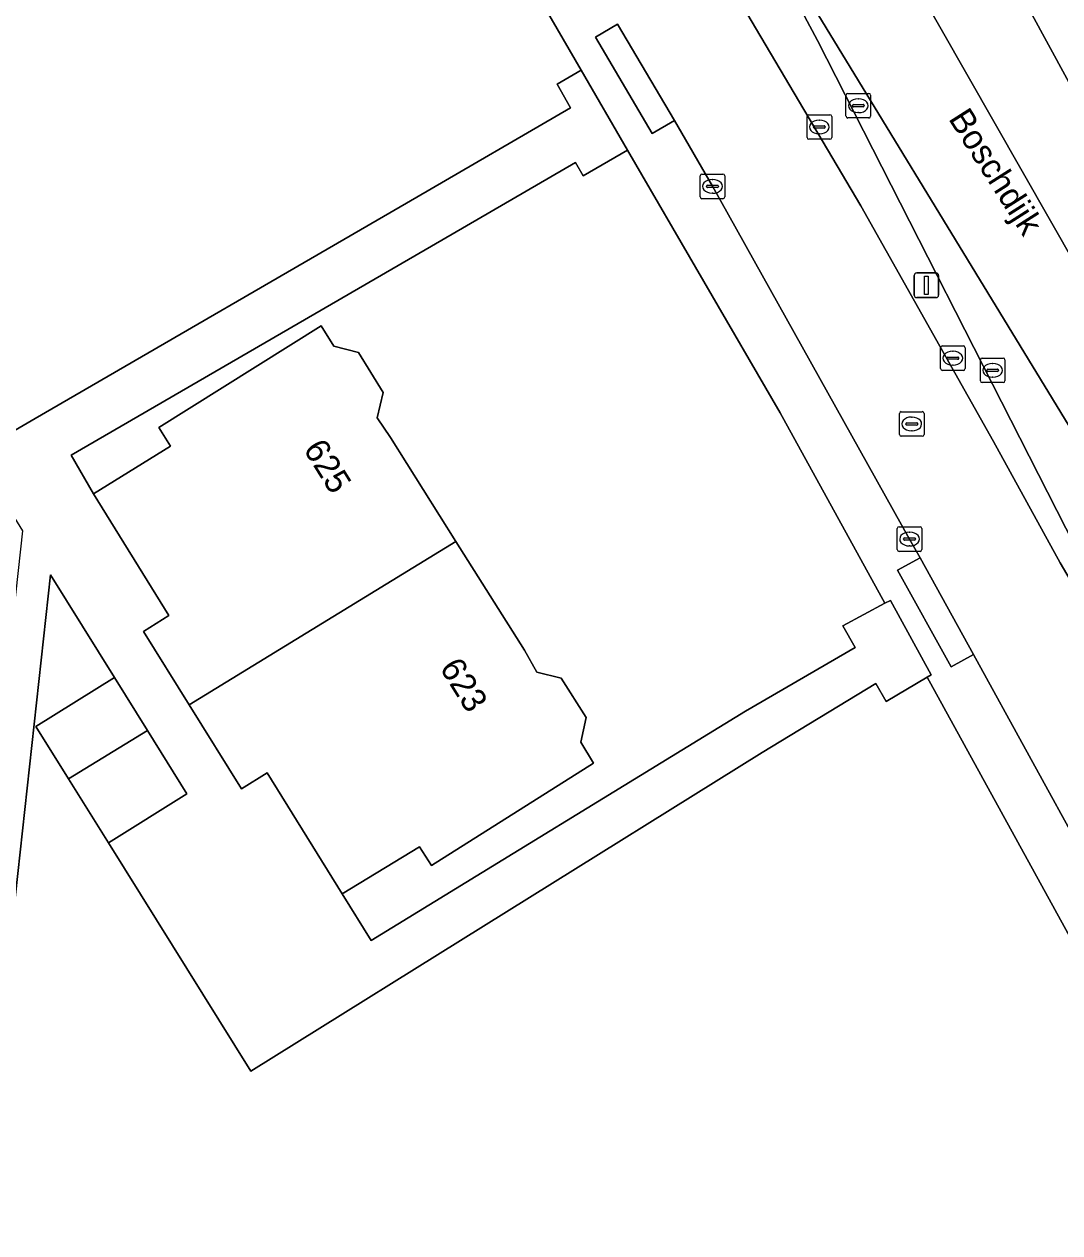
# Model space of a CAD drawing. Extents: x 158132 to 159664, y 385256 to 387218.
# Drawn here: x 159568.91 to 159611, y 385917.16 to 385966.28 of the extents above; entities that cross this region are included whole.
import ezdxf

# ---------------------------------------------------------------- set-up
doc = ezdxf.new("R2010")
doc.units = 0
for name, color, linetype in [('IMGEO_Berm_groen', 7, 'Continuous'), ('IMGEO_Berm_open', 7, 'Continuous'), ('IMGEO_Erf', 7, 'Continuous'), ('IMGEO_Groenvoorziening', 7, 'Continuous'), ('IMGEO_Kolk', 7, 'Continuous'), ('IMGEO_Lichtmast', 7, 'Continuous'), ('IMGEO_Openbare_ruimte_label', 7, 'Continuous'), ('IMGEO_Pand', 7, 'Continuous'), ('IMGEO_Pand_nummerreeks', 7, 'Continuous'), ('IMGEO_Rijbaan_lokaal_open', 7, 'Continuous'), ('IMGEO_Rijbaan_regionaal_gesloten', 7, 'Continuous'), ('IMGEO_Rioolput', 7, 'Continuous'), ('IMGEO_Voetpad_open', 7, 'Continuous')]:
    doc.layers.add(name, color=color, linetype=linetype)

msp = doc.modelspace()

# ---------------------------------------------------------------- linework, layer by layer
at = {"layer": 'IMGEO_Berm_groen'}
msp.add_lwpolyline([(159575.204, 385998.555), (159579.934, 385993.03), (159585.402, 385986.335), (159589.628, 385980.657), (159593.949, 385974.057), (159597.879, 385967.409), (159602.91, 385958.899), (159608.296, 385949.322), (159611.008, 385944.38), (159614.046, 385939.227), (159614.705, 385939.573), (159611.619, 385945.057), (159601.152, 385965.61), (159596.488, 385974.358), (159593.823, 385978.986), (159590.929, 385983.677), (159587.286, 385989.429), (159582.268, 385997.49)], dxfattribs=at)
at = {"layer": 'IMGEO_Berm_open'}
msp.add_lwpolyline([(159590.289, 385999.259), (159593.396, 385994.269), (159596.933, 385988.677), (159599.683, 385984.229), (159601.113, 385981.934), (159602.622, 385979.469), (159604.449, 385976.284), (159609.132, 385968.039), (159611.944, 385962.856), (159614.131, 385959.461), (159617.02, 385955.345), (159626.869, 385941.335), (159627.24, 385940.801), (159632.235, 385932.811), (159633.744, 385930.178), (159648.597, 385904.404), (159649.117, 385903.501)], dxfattribs=at)
at = {"layer": 'IMGEO_Erf'}
msp.add_lwpolyline([(159599.633, 385950.479), (159593.433, 385961.16), (159591.631, 385960.115), (159591.314, 385960.661), (159585.878, 385957.505), (159570.82, 385948.764), (159571.73, 385947.196), (159574.852, 385949.125), (159574.379, 385949.891), (159580.975, 385954.016), (159581.491, 385953.191), (159582.502, 385952.937), (159583.497, 385951.309), (159583.252, 385950.282), (159583.789, 385949.474), (159586.449, 385945.253), (159589.236, 385940.832), (159589.747, 385939.942), (159590.737, 385939.699), (159591.741, 385938.097), (159591.535, 385937.094), (159592.051, 385936.239), (159585.46, 385932.081), (159584.978, 385932.841), (159581.834, 385930.927), (159583.005, 385929.039), (159598.227, 385938.364), (159602.681, 385940.944), (159602.181, 385941.82), (159603.878, 385942.752)], close=True, dxfattribs=at)
at = {"layer": 'IMGEO_Groenvoorziening'}
for points in [[(159591.547, 385964.41), (159586.231, 385973.567), (159582.66, 385978.825)], [(159565.497, 385915.064), (159568.861, 385945.693), (159566.907, 385948.83), (159569.362, 385950.255), (159584.863, 385959.253), (159591.117, 385962.883), (159590.563, 385963.838), (159591.547, 385964.41)], [(159612.976, 385926.325), (159605.6, 385939.741), (159603.939, 385938.744), (159603.517, 385939.481), (159598.897, 385936.678), (159578.119, 385923.72), (159572.33, 385933.002), (159570.708, 385935.608), (159569.385, 385937.734), (159572.576, 385939.724), (159569.982, 385943.892), (159566.84, 385915.285)]]:
    msp.add_lwpolyline(points, dxfattribs=at)
at = {"layer": 'IMGEO_Kolk'}
for p, q in [((159602.381, 385963.466), (159603.233, 385963.466)), ((159602.306, 385962.54), (159602.306, 385963.392)), ((159602.565, 385962.96), (159602.565, 385962.972)), ((159602.608, 385963.009), (159603.006, 385963.009)), ((159602.794, 385963.246), (159602.819, 385963.246)), ((159603.049, 385962.972), (159603.049, 385962.96)), ((159603.307, 385963.392), (159603.307, 385962.54)), ((159600.723, 385961.674), (159600.723, 385962.526)), ((159600.798, 385962.6), (159601.65, 385962.6)), ((159601.724, 385962.526), (159601.724, 385961.674)), ((159603.233, 385962.466), (159602.381, 385962.466)), ((159603.003, 385962.923), (159602.605, 385962.923)), ((159602.817, 385962.686), (159602.792, 385962.686)), ((159600.982, 385962.094), (159600.982, 385962.106)), ((159601.42, 385962.057), (159601.022, 385962.057)), ((159601.025, 385962.143), (159601.423, 385962.143)), ((159601.211, 385962.38), (159601.236, 385962.38)), ((159601.466, 385962.106), (159601.466, 385962.094)), ((159601.65, 385961.6), (159600.798, 385961.6)), ((159601.234, 385961.82), (159601.209, 385961.82)), ((159596.379, 385959.261), (159596.379, 385960.113)), ((159596.454, 385960.187), (159597.306, 385960.187)), ((159597.38, 385960.113), (159597.38, 385959.261)), ((159596.638, 385959.681), (159596.638, 385959.693)), ((159597.076, 385959.644), (159596.678, 385959.644)), ((159596.681, 385959.73), (159597.079, 385959.73)), ((159596.867, 385959.967), (159596.892, 385959.967)), ((159597.122, 385959.693), (159597.122, 385959.681)), ((159597.306, 385959.187), (159596.454, 385959.187)), ((159596.89, 385959.407), (159596.865, 385959.407)), ((159606.148, 385952.278), (159606.148, 385953.13)), ((159606.223, 385953.204), (159607.075, 385953.204)), ((159607.149, 385953.13), (159607.149, 385952.278)), ((159606.407, 385952.698), (159606.407, 385952.71)), ((159606.845, 385952.661), (159606.447, 385952.661)), ((159606.45, 385952.747), (159606.848, 385952.747)), ((159606.636, 385952.984), (159606.661, 385952.984)), ((159606.891, 385952.71), (159606.891, 385952.698)), ((159607.766, 385951.784), (159607.766, 385952.636)), ((159607.841, 385952.71), (159608.693, 385952.71)), ((159608.767, 385952.636), (159608.767, 385951.784)), ((159607.075, 385952.204), (159606.223, 385952.204)), ((159606.659, 385952.424), (159606.634, 385952.424)), ((159608.025, 385952.204), (159608.025, 385952.216)), ((159608.463, 385952.167), (159608.065, 385952.167)), ((159608.068, 385952.253), (159608.466, 385952.253)), ((159608.254, 385952.49), (159608.279, 385952.49)), ((159608.509, 385952.216), (159608.509, 385952.204)), ((159608.693, 385951.71), (159607.841, 385951.71)), ((159608.277, 385951.93), (159608.252, 385951.93)), ((159604.388, 385944.927), (159604.388, 385945.779)), ((159604.463, 385945.853), (159605.315, 385945.853)), ((159605.389, 385945.779), (159605.389, 385944.927)), ((159604.647, 385945.347), (159604.647, 385945.359)), ((159605.085, 385945.31), (159604.687, 385945.31)), ((159604.69, 385945.396), (159605.088, 385945.396)), ((159604.876, 385945.633), (159604.901, 385945.633)), ((159605.131, 385945.359), (159605.131, 385945.347)), ((159605.315, 385944.853), (159604.463, 385944.853)), ((159604.899, 385945.073), (159604.874, 385945.073))]:
    msp.add_line(p, q, dxfattribs=at)
for points in [[(159602.381, 385963.466), (159603.233, 385963.466)], [(159602.306, 385962.54), (159602.306, 385963.392)], [(159603.307, 385963.392), (159603.307, 385962.54)], [(159600.723, 385961.674), (159600.723, 385962.526)], [(159600.798, 385962.6), (159601.65, 385962.6)], [(159601.724, 385962.526), (159601.724, 385961.674)], [(159603.233, 385962.466), (159602.381, 385962.466)], [(159601.65, 385961.6), (159600.798, 385961.6)], [(159596.379, 385959.261), (159596.379, 385960.113)], [(159596.454, 385960.187), (159597.306, 385960.187)], [(159597.38, 385960.113), (159597.38, 385959.261)], [(159597.306, 385959.187), (159596.454, 385959.187)], [(159606.148, 385952.278), (159606.148, 385953.13)], [(159606.223, 385953.204), (159607.075, 385953.204)], [(159607.149, 385953.13), (159607.149, 385952.278)], [(159607.766, 385951.784), (159607.766, 385952.636)], [(159607.841, 385952.71), (159608.693, 385952.71)], [(159608.767, 385952.636), (159608.767, 385951.784)], [(159607.075, 385952.204), (159606.223, 385952.204)], [(159608.693, 385951.71), (159607.841, 385951.71)], [(159604.388, 385944.927), (159604.388, 385945.779)], [(159604.463, 385945.853), (159605.315, 385945.853)], [(159605.389, 385945.779), (159605.389, 385944.927)], [(159605.315, 385944.853), (159604.463, 385944.853)]]:
    msp.add_lwpolyline(points, dxfattribs=at)
for centre, radius, start, end in [((159602.383, 385963.39), 0.0765, 91.552, 178.448), ((159602.383, 385963.39), 0.0765, 91.552, 178.448), ((159603.231, 385963.39), 0.0765, 1.552, 88.448), ((159603.231, 385963.39), 0.0765, 1.552, 88.448), ((159602.605, 385962.969), 0.0403, 85.8775, 175.7526), ((159602.602, 385962.959), 0.0366, 178.938, 274.7102), ((159603.006, 385962.966), 0.043, 264.8664, 352.4533), ((159603.01, 385962.971), 0.0386, 1.7309, 96.639), ((159600.8, 385962.524), 0.0765, 91.552, 178.448), ((159600.8, 385962.524), 0.0765, 91.552, 178.448), ((159601.648, 385962.524), 0.0765, 1.552, 88.448), ((159601.648, 385962.524), 0.0765, 1.552, 88.448), ((159602.383, 385962.542), 0.0765, 181.552, 268.448), ((159602.383, 385962.542), 0.0765, 181.552, 268.448), ((159603.231, 385962.542), 0.0765, 271.552, 358.448), ((159603.231, 385962.542), 0.0765, 271.552, 358.448), ((159601.022, 385962.103), 0.0403, 85.8775, 175.7526), ((159601.019, 385962.093), 0.0366, 178.938, 274.7102), ((159601.423, 385962.1), 0.043, 264.8664, 352.4533), ((159601.427, 385962.105), 0.0386, 1.7309, 96.639), ((159600.8, 385961.676), 0.0765, 181.552, 268.448), ((159600.8, 385961.676), 0.0765, 181.552, 268.448), ((159601.648, 385961.676), 0.0765, 271.552, 358.448), ((159601.648, 385961.676), 0.0765, 271.552, 358.448), ((159596.456, 385960.111), 0.0765, 91.552, 178.448), ((159596.456, 385960.111), 0.0765, 91.552, 178.448), ((159597.304, 385960.111), 0.0765, 1.552, 88.448), ((159597.304, 385960.111), 0.0765, 1.552, 88.448), ((159596.678, 385959.69), 0.0403, 85.8775, 175.7526), ((159596.675, 385959.68), 0.0366, 178.938, 274.7102), ((159597.079, 385959.687), 0.043, 264.8664, 352.4533), ((159597.083, 385959.692), 0.0386, 1.7309, 96.639), ((159596.456, 385959.263), 0.0765, 181.552, 268.448), ((159596.456, 385959.263), 0.0765, 181.552, 268.448), ((159597.304, 385959.263), 0.0765, 271.552, 358.448), ((159597.304, 385959.263), 0.0765, 271.552, 358.448), ((159606.225, 385953.128), 0.0765, 91.552, 178.448), ((159606.225, 385953.128), 0.0765, 91.552, 178.448), ((159607.073, 385953.128), 0.0765, 1.552, 88.448), ((159607.073, 385953.128), 0.0765, 1.552, 88.448), ((159606.447, 385952.707), 0.0403, 85.8775, 175.7526), ((159606.444, 385952.697), 0.0366, 178.938, 274.7102), ((159606.848, 385952.704), 0.043, 264.8664, 352.4533), ((159606.852, 385952.709), 0.0386, 1.7309, 96.639), ((159607.843, 385952.634), 0.0765, 91.552, 178.448), ((159607.843, 385952.634), 0.0765, 91.552, 178.448), ((159608.691, 385952.634), 0.0765, 1.552, 88.448), ((159608.691, 385952.634), 0.0765, 1.552, 88.448), ((159606.225, 385952.28), 0.0765, 181.552, 268.448), ((159606.225, 385952.28), 0.0765, 181.552, 268.448), ((159607.073, 385952.28), 0.0765, 271.552, 358.448), ((159607.073, 385952.28), 0.0765, 271.552, 358.448), ((159608.065, 385952.213), 0.0403, 85.8775, 175.7526), ((159608.062, 385952.203), 0.0366, 178.938, 274.7102), ((159608.466, 385952.21), 0.043, 264.8664, 352.4533), ((159608.47, 385952.215), 0.0386, 1.7309, 96.639), ((159607.843, 385951.786), 0.0765, 181.552, 268.448), ((159607.843, 385951.786), 0.0765, 181.552, 268.448), ((159608.691, 385951.786), 0.0765, 271.552, 358.448), ((159608.691, 385951.786), 0.0765, 271.552, 358.448), ((159604.465, 385945.777), 0.0765, 91.552, 178.448), ((159604.465, 385945.777), 0.0765, 91.552, 178.448), ((159605.313, 385945.777), 0.0765, 1.552, 88.448), ((159605.313, 385945.777), 0.0765, 1.552, 88.448), ((159604.687, 385945.356), 0.0403, 85.8775, 175.7526), ((159604.684, 385945.346), 0.0366, 178.938, 274.7102), ((159605.088, 385945.353), 0.043, 264.8664, 352.4533), ((159605.092, 385945.358), 0.0386, 1.7309, 96.639), ((159604.465, 385944.929), 0.0765, 181.552, 268.448), ((159604.465, 385944.929), 0.0765, 181.552, 268.448), ((159605.313, 385944.929), 0.0765, 271.552, 358.448), ((159605.313, 385944.929), 0.0765, 271.552, 358.448)]:
    msp.add_arc(centre, radius, start, end, dxfattribs=at)
for centre, major_axis, ratio, start_param, end_param in [((159602.793, 385962.966), (-0.387, 0.002), 0.722429, 4.712389, 7.853982), ((159602.818, 385962.966), (-0.39, 0.002), 0.717154, 1.570796, 4.712389), ((159601.21, 385962.1), (-0.387, 0.002), 0.722429, 4.712389, 7.853982), ((159601.235, 385962.1), (-0.39, 0.002), 0.717154, 1.570796, 4.712389), ((159596.866, 385959.687), (-0.387, 0.002), 0.722429, 4.712389, 7.853982), ((159596.891, 385959.687), (-0.39, 0.002), 0.717154, 1.570796, 4.712389), ((159606.635, 385952.704), (-0.387, 0.002), 0.722429, 4.712389, 7.853982), ((159606.66, 385952.704), (-0.39, 0.002), 0.717154, 1.570796, 4.712389), ((159608.253, 385952.21), (-0.387, 0.002), 0.722429, 4.712389, 7.853982), ((159608.278, 385952.21), (-0.39, 0.002), 0.717154, 1.570796, 4.712389), ((159604.875, 385945.353), (-0.387, 0.002), 0.722429, 4.712389, 7.853982), ((159604.9, 385945.353), (-0.39, 0.002), 0.717154, 1.570796, 4.712389)]:
    msp.add_ellipse(centre, major_axis=major_axis, ratio=ratio, start_param=start_param, end_param=end_param, dxfattribs=at)
at = {"layer": 'IMGEO_Lichtmast'}
for p, q in [((159605.079, 385955.267), (159605.079, 385956.067)), ((159605.079, 385956.067), (159605.079, 385955.267)), ((159605.179, 385956.167), (159605.969, 385956.167)), ((159605.969, 385956.167), (159605.179, 385956.167)), ((159606.069, 385956.067), (159606.069, 385955.267)), ((159606.069, 385955.267), (159606.069, 385956.067)), ((159605.969, 385955.167), (159605.179, 385955.167)), ((159605.179, 385955.167), (159605.969, 385955.167))]:
    msp.add_line(p, q, dxfattribs=at)
msp.add_lwpolyline([(159605.499, 385956.042), (159605.649, 385956.042), (159605.649, 385955.292), (159605.499, 385955.292), (159605.499, 385956.042)], dxfattribs=at)
for centre, start, end in [((159605.179, 385956.067), 90, 180), ((159605.179, 385956.067), 90, 180), ((159605.969, 385956.067), 0, 90), ((159605.969, 385956.067), 360, 90), ((159605.179, 385955.267), 180, 270), ((159605.179, 385955.267), 180, 270), ((159605.969, 385955.267), 270, 0), ((159605.969, 385955.267), 270, 0)]:
    msp.add_arc(centre, 0.1, start, end, dxfattribs=at)
at = {"layer": 'IMGEO_Pand'}
for points in [[(159586.449, 385945.253), (159583.789, 385949.474), (159583.252, 385950.282), (159583.497, 385951.309), (159582.502, 385952.937), (159581.491, 385953.191), (159580.975, 385954.016), (159574.379, 385949.891), (159574.852, 385949.125), (159571.73, 385947.196), (159574.787, 385942.247), (159573.752, 385941.601), (159575.615, 385938.615)], [(159586.449, 385945.253), (159575.615, 385938.615), (159577.746, 385935.2), (159578.781, 385935.847), (159581.834, 385930.927), (159584.978, 385932.841), (159585.46, 385932.081), (159592.051, 385936.239), (159591.535, 385937.094), (159591.741, 385938.097), (159590.737, 385939.699), (159589.747, 385939.942), (159589.236, 385940.832)], [(159570.708, 385935.608), (159573.915, 385937.573), (159572.576, 385939.724), (159569.385, 385937.734)], [(159570.708, 385935.608), (159572.33, 385933.002), (159575.521, 385934.992), (159573.915, 385937.573)]]:
    msp.add_lwpolyline(points, close=True, dxfattribs=at)
at = {"layer": 'IMGEO_Rijbaan_lokaal_open'}
for points in [[(159625.723, 385917.698), (159624.803, 385919.32), (159622.894, 385922.952), (159621.218, 385926.097), (159618.816, 385930.485), (159614.046, 385939.227), (159611.008, 385944.38), (159608.296, 385949.322), (159602.91, 385958.899), (159597.879, 385967.409), (159593.949, 385974.057), (159589.628, 385980.657), (159585.402, 385986.335), (159579.934, 385993.03), (159575.204, 385998.555)], [(159593.025, 385966.279), (159595.331, 385962.368), (159596.877, 385959.69), (159604.892, 385945.35), (159605.315, 385944.586), (159607.486, 385940.665), (159614.277, 385928.306), (159622.049, 385914.2), (159624.06, 385910.558), (159624.148, 385910.573), (159625.119, 385910.687), (159626.096, 385910.713), (159627.072, 385910.653), (159628.038, 385910.505)]]:
    msp.add_lwpolyline(points, dxfattribs=at)
at = {"layer": 'IMGEO_Rijbaan_regionaal_gesloten'}
for points in [[(159499.651, 386137.219), (159496.379, 386135.29), (159503.232, 386124.33), (159517.304, 386101.878), (159529.011, 386083.065), (159545.802, 386056.241), (159576.14, 386007.176), (159580.646, 386000.222), (159582.268, 385997.49), (159587.286, 385989.429), (159590.929, 385983.677), (159593.823, 385978.986), (159596.488, 385974.358), (159598.531, 385971.012), (159611.522, 385949.695), (159641.915, 385897.112), (159642.042, 385896.892), (159644.386, 385899.081), (159644.13, 385899.529), (159600.527, 385975.989), (159574.471, 386016.885), (159520.444, 386103.637)], [(159596.488, 385974.358), (159601.152, 385965.61), (159611.619, 385945.057), (159614.705, 385939.573), (159619.492, 385930.188), (159620.936, 385927.556), (159626.382, 385918.054), (159634.618, 385903.691), (159635.002, 385903.043), (159635.137, 385902.822), (159639.755, 385894.755), (159642.042, 385896.892), (159641.915, 385897.112), (159611.522, 385949.695), (159598.531, 385971.012)]]:
    msp.add_lwpolyline(points, close=True, dxfattribs=at)
msp.add_lwpolyline([(159574.471, 386016.885), (159600.527, 385975.989), (159644.13, 385899.529), (159644.386, 385899.081), (159646.73, 385901.271), (159646.344, 385901.945), (159618.413, 385950.738), (159611.944, 385962.856), (159609.132, 385968.039), (159604.449, 385976.284), (159602.622, 385979.469), (159601.113, 385981.934), (159599.683, 385984.229), (159596.933, 385988.677), (159593.396, 385994.269), (159590.289, 385999.259)], dxfattribs=at)
at = {"layer": 'IMGEO_Rioolput'}
for p, q in [((159604.479, 385949.604), (159604.479, 385950.456)), ((159604.554, 385950.53), (159605.406, 385950.53)), ((159604.967, 385950.31), (159604.992, 385950.31)), ((159605.48, 385950.456), (159605.48, 385949.604)), ((159604.738, 385950.024), (159604.738, 385950.036)), ((159605.176, 385949.987), (159604.778, 385949.987)), ((159604.781, 385950.073), (159605.179, 385950.073)), ((159604.99, 385949.75), (159604.965, 385949.75)), ((159605.222, 385950.036), (159605.222, 385950.024)), ((159605.406, 385949.53), (159604.554, 385949.53))]:
    msp.add_line(p, q, dxfattribs=at)
for points in [[(159604.479, 385949.604), (159604.479, 385950.456)], [(159604.554, 385950.53), (159605.406, 385950.53)], [(159605.48, 385950.456), (159605.48, 385949.604)], [(159605.406, 385949.53), (159604.554, 385949.53)]]:
    msp.add_lwpolyline(points, dxfattribs=at)
for centre, radius, start, end in [((159604.556, 385950.454), 0.0765, 91.552, 178.448), ((159604.556, 385950.454), 0.0765, 91.552, 178.448), ((159605.404, 385950.454), 0.0765, 1.552, 88.448), ((159605.404, 385950.454), 0.0765, 1.552, 88.448), ((159604.778, 385950.033), 0.0403, 85.8775, 175.7526), ((159604.775, 385950.023), 0.0366, 178.938, 274.7102), ((159605.179, 385950.03), 0.043, 264.8664, 352.4533), ((159605.183, 385950.035), 0.0386, 1.7309, 96.639), ((159604.556, 385949.606), 0.0765, 181.552, 268.448), ((159604.556, 385949.606), 0.0765, 181.552, 268.448), ((159605.404, 385949.606), 0.0765, 271.552, 358.448), ((159605.404, 385949.606), 0.0765, 271.552, 358.448)]:
    msp.add_arc(centre, radius, start, end, dxfattribs=at)
for centre, major_axis, ratio, start_param, end_param in [((159604.966, 385950.03), (-0.387, 0.002), 0.722429, 4.712389, 7.853982), ((159604.991, 385950.03), (-0.39, 0.002), 0.717154, 1.570796, 4.712389)]:
    msp.add_ellipse(centre, major_axis=major_axis, ratio=ratio, start_param=start_param, end_param=end_param, dxfattribs=at)
at = {"layer": 'IMGEO_Voetpad_open'}
for points in [[(159582.66, 385978.825), (159586.231, 385973.567), (159591.547, 385964.41), (159593.433, 385961.16), (159599.633, 385950.479), (159603.878, 385942.752), (159604.109, 385942.858), (159605.764, 385939.828), (159605.6, 385939.741), (159612.976, 385926.325), (159620.297, 385913.244), (159622.049, 385914.2), (159614.277, 385928.306), (159607.486, 385940.665), (159606.576, 385940.161), (159604.405, 385944.082), (159605.315, 385944.586), (159604.892, 385945.35), (159596.877, 385959.69), (159595.331, 385962.368), (159594.435, 385961.84), (159592.129, 385965.751), (159593.025, 385966.279)], [(159566.84, 385915.285), (159569.982, 385943.892), (159572.576, 385939.724), (159573.915, 385937.573), (159575.521, 385934.992), (159572.33, 385933.002), (159578.119, 385923.72), (159598.897, 385936.678), (159603.517, 385939.481), (159603.939, 385938.744), (159605.6, 385939.741), (159605.764, 385939.828), (159604.109, 385942.858), (159603.878, 385942.752), (159602.181, 385941.82), (159602.681, 385940.944), (159598.227, 385938.364), (159583.005, 385929.039), (159581.834, 385930.927), (159578.781, 385935.847), (159577.746, 385935.2), (159575.615, 385938.615), (159573.752, 385941.601), (159574.787, 385942.247), (159571.73, 385947.196), (159570.82, 385948.764), (159585.878, 385957.505), (159591.314, 385960.661), (159591.631, 385960.115), (159593.433, 385961.16), (159591.547, 385964.41), (159590.563, 385963.838), (159591.117, 385962.883), (159584.863, 385959.253), (159569.362, 385950.255), (159566.907, 385948.83)]]:
    msp.add_lwpolyline(points, dxfattribs=at)
for points in [[(159593.025, 385966.279), (159592.129, 385965.751), (159594.435, 385961.84), (159595.331, 385962.368)], [(159605.315, 385944.586), (159604.405, 385944.082), (159606.576, 385940.161), (159607.486, 385940.665)]]:
    msp.add_lwpolyline(points, close=True, dxfattribs=at)

# ---------------------------------------------------------------- texts
at = {"layer": 'IMGEO_Openbare_ruimte_label'}
msp.add_text('Boschdijk', height=1, rotation=302.4668, dxfattribs=at).set_placement((159606.446, 385962.438))
at = {"layer": 'IMGEO_Pand_nummerreeks'}
for s, p in [('625', (159580.231, 385949.007)), ('623', (159585.769, 385940.119))]:
    msp.add_text(s, height=1, rotation=301.9251, dxfattribs=at).set_placement(p)

doc.saveas('drawing.dxf')
